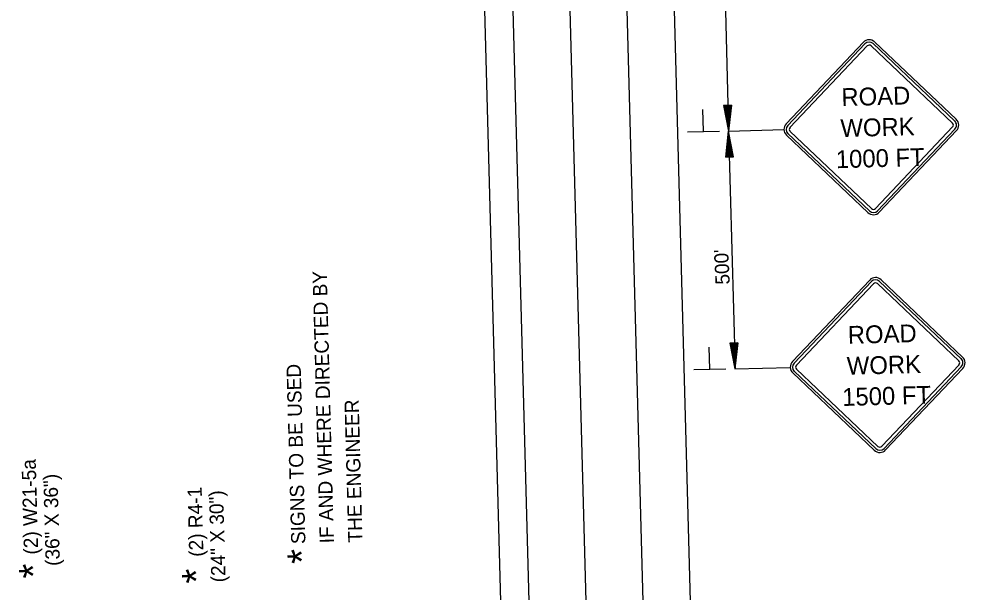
# Model space of a CAD drawing. Extents: x 1930579 to 1931593, y 596452 to 598537.
# Drawn here: x 1930685 to 1931083.1, y 597318.3 to 597559.3 of the extents above; entities that cross this region are included whole.
import ezdxf

# ---------------------------------------------------------------- set-up
doc = ezdxf.new("R2010")
doc.units = 0
for name, color, linetype in [('P_TC_Signs_Temporary', 7, 'Continuous'), ('R_Annotation', 7, 'Continuous'), ('R_Border', 7, 'Continuous'), ('R_Draft', 7, 'Continuous')]:
    doc.layers.add(name, color=color, linetype=linetype)

msp = doc.modelspace()

# ---------------------------------------------------------------- linework, layer by layer
at = {"layer": 'P_TC_Signs_Temporary'}
for p, q in [((1931007.83, 597515.18), (1931040.33, 597549.47)), ((1931008.51, 597514.53), (1931041.01, 597548.83)), ((1931009.46, 597513.63), (1931041.97, 597547.93)), ((1931043.56, 597547.97), (1931077.85, 597515.47)), ((1931044.46, 597548.92), (1931078.75, 597516.42)), ((1931045.1, 597549.6), (1931079.4, 597517.1)), ((1931042.9, 597478.58), (1931008.6, 597511.09)), ((1931043.8, 597479.54), (1931009.51, 597512.04)), ((1931077.89, 597513.88), (1931045.39, 597479.58)), ((1931078.85, 597512.97), (1931046.35, 597478.68)), ((1931079.53, 597512.33), (1931047.03, 597478.03)), ((1931042.25, 597477.9), (1931007.96, 597510.41)), ((1931010.51, 597415.21), (1931043.02, 597449.51)), ((1931011.19, 597414.57), (1931043.7, 597448.86)), ((1931012.15, 597413.67), (1931044.65, 597447.96)), ((1931046.24, 597448), (1931080.54, 597415.5)), ((1931047.14, 597448.96), (1931081.44, 597416.45)), ((1931047.79, 597449.64), (1931082.08, 597417.13)), ((1931046.49, 597379.57), (1931012.19, 597412.08)), ((1931080.58, 597413.91), (1931048.08, 597379.62)), ((1931081.53, 597413.01), (1931049.03, 597378.71)), ((1931082.21, 597412.36), (1931049.71, 597378.07)), ((1931044.94, 597377.94), (1931010.64, 597410.44)), ((1931045.58, 597378.62), (1931011.29, 597411.12))]:
    msp.add_line(p, q, dxfattribs=at)
for centre, radius, start, end in [((1931042.78, 597547.15), 3.38, 46.5377, 136.5377), ((1931042.78, 597547.15), 2.44, 46.5377, 136.5377), ((1931042.78, 597547.15), 1.13, 46.5377, 136.5377), ((1931010.28, 597512.86), 3.38, 136.5377, 226.5377), ((1931077.08, 597514.65), 1.12, 316.5377, 46.5377), ((1931077.08, 597514.65), 2.44, 316.5377, 46.5377), ((1931077.08, 597514.65), 3.38, 316.5377, 46.5377), ((1931010.28, 597512.86), 2.44, 136.5377, 226.5377), ((1931010.28, 597512.86), 1.12, 136.5377, 226.5377), ((1931044.58, 597480.35), 1.13, 226.5377, 316.5377), ((1931044.58, 597480.35), 3.38, 226.5377, 316.5377), ((1931044.58, 597480.35), 2.44, 226.5377, 316.5377), ((1931045.47, 597447.19), 3.38, 46.5377, 136.5377), ((1931045.47, 597447.19), 2.44, 46.5377, 136.5377), ((1931045.47, 597447.19), 1.13, 46.5377, 136.5377), ((1931012.96, 597412.89), 3.38, 136.5377, 226.5377), ((1931079.76, 597414.69), 1.12, 316.5377, 46.5377), ((1931079.76, 597414.69), 2.44, 316.5377, 46.5377), ((1931079.76, 597414.69), 3.38, 316.5377, 46.5377), ((1931012.96, 597412.89), 2.44, 136.5377, 226.5377), ((1931012.96, 597412.89), 1.12, 136.5377, 226.5377), ((1931047.26, 597380.39), 1.13, 226.5377, 316.5377), ((1931047.26, 597380.39), 3.38, 226.5377, 316.5377), ((1931047.26, 597380.39), 2.44, 226.5377, 316.5377)]:
    msp.add_arc(centre, radius, start, end, dxfattribs=at)
at = {"layer": 'R_Draft'}
for p, q in [((1930889.59, 597245.72), (1930877.94, 597679.58)), ((1930901.55, 597246.05), (1930889.9, 597679.9)), ((1930925.48, 597246.69), (1930913.83, 597680.54)), ((1930949.41, 597247.33), (1930937.76, 597681.18)), ((1930969.35, 597247.87), (1930957.71, 597681.72)), ((1930980.94, 597612.1), (1930983.62, 597512.14)), ((1930984.78, 597523.08), (1930981.52, 597522.94)), ((1930981.52, 597522.94), (1930983.62, 597512.14)), ((1930981.8, 597522.95), (1930983.54, 597513.96)), ((1930982.07, 597522.97), (1930983.46, 597515.82)), ((1930982.34, 597522.98), (1930983.38, 597517.64)), ((1930982.62, 597522.99), (1930983.3, 597519.48)), ((1930982.9, 597523), (1930983.22, 597521.3)), ((1930983.41, 597523.02), (1930983.22, 597521.3)), ((1930983.68, 597523.03), (1930983.3, 597519.48)), ((1930983.96, 597523.04), (1930983.38, 597517.64)), ((1930984.23, 597523.06), (1930983.46, 597515.82)), ((1930984.51, 597523.07), (1930983.54, 597513.96)), ((1930984.78, 597523.08), (1930983.62, 597512.14)), ((1930973.07, 597512.05), (1930972.82, 597521.24)), ((1930979.77, 597512.04), (1930966.31, 597511.68)), ((1930982.46, 597501.2), (1930983.62, 597512.14)), ((1930983.62, 597512.14), (1931006.91, 597512.77)), ((1930983.62, 597512.14), (1930986.33, 597412.3)), ((1930985.72, 597501.34), (1930983.62, 597512.14)), ((1930982.73, 597501.21), (1930983.7, 597510.32)), ((1930983.01, 597501.23), (1930983.78, 597508.46)), ((1930985.45, 597501.33), (1930983.7, 597510.32)), ((1930985.17, 597501.31), (1930983.78, 597508.46)), ((1930983.28, 597501.24), (1930983.86, 597506.65)), ((1930983.56, 597501.25), (1930983.93, 597504.8)), ((1930983.83, 597501.26), (1930984.01, 597502.99)), ((1930984.9, 597501.3), (1930983.86, 597506.65)), ((1930984.62, 597501.29), (1930983.93, 597504.8)), ((1930984.34, 597501.28), (1930984.01, 597502.99)), ((1930982.46, 597501.2), (1930985.72, 597501.34)), ((1930987.46, 597423.12), (1930984.2, 597422.98)), ((1930987.46, 597423.12), (1930986.3, 597412.18)), ((1930975.75, 597412.09), (1930975.5, 597421.27)), ((1930984.2, 597422.98), (1930986.3, 597412.18)), ((1930984.48, 597422.99), (1930986.22, 597413.99)), ((1930984.76, 597423), (1930986.14, 597415.86)), ((1930985.03, 597423.01), (1930986.06, 597417.67)), ((1930985.3, 597423.03), (1930985.99, 597419.52)), ((1930985.58, 597423.04), (1930985.91, 597421.33)), ((1930986.09, 597423.06), (1930985.91, 597421.33)), ((1930986.36, 597423.07), (1930985.99, 597419.52)), ((1930986.64, 597423.08), (1930986.06, 597417.67)), ((1930986.92, 597423.09), (1930986.14, 597415.86)), ((1930987.2, 597423.1), (1930986.22, 597413.99)), ((1930982.45, 597412.07), (1930968.99, 597411.71)), ((1930986.3, 597412.18), (1931009.59, 597412.8))]:
    msp.add_line(p, q, dxfattribs=at)

# ---------------------------------------------------------------- texts
at = {"layer": 'P_TC_Signs_Temporary'}
for s, p in [(' ROAD ', (1931028.42, 597522.56)), ('WORK', (1931030.8, 597509.6)), ('1000 FT', (1931028.85, 597496.52)), (' ROAD ', (1931031.1, 597422.59)), ('WORK', (1931033.48, 597409.63)), ('1500 FT', (1931031.53, 597396.55))]:
    msp.add_text(s, height=7.5, rotation=1.5377, dxfattribs=at).set_placement(p)
at = {"layer": 'R_Annotation'}
for s, p in [('(2) W21-5a', (1930693.13, 597334.16)), ('(36" X 36")', (1930702.26, 597329.4)), ('(2) R4-1', (1930762.67, 597333.24)), ('(24" X 30")', (1930771.97, 597322.48))]:
    msp.add_text(s, height=6, rotation=91.5377, dxfattribs=at).set_placement(p)
at = {"layer": 'R_Border'}
for p in [(1930810.09, 597330.4), (1930697.09, 597324.27), (1930765.68, 597322.14)]:
    msp.add_text('*', height=12, rotation=91.5377, dxfattribs=at).set_placement(p)
at = {"layer": 'R_Draft'}
for s, rotation, p in [("500'", 92.7681, (1930984.15, 597447.72)), ('IF AND WHERE DIRECTED BY', 91.5377, (1930817.59, 597338.89)), ('SIGNS TO BE USED', 91.5377, (1930805.59, 597338.57)), ('THE ENGINEER', 91.5377, (1930829.59, 597339.21))]:
    msp.add_text(s, height=6, rotation=rotation, dxfattribs=at).set_placement(p)

doc.saveas('drawing.dxf')
